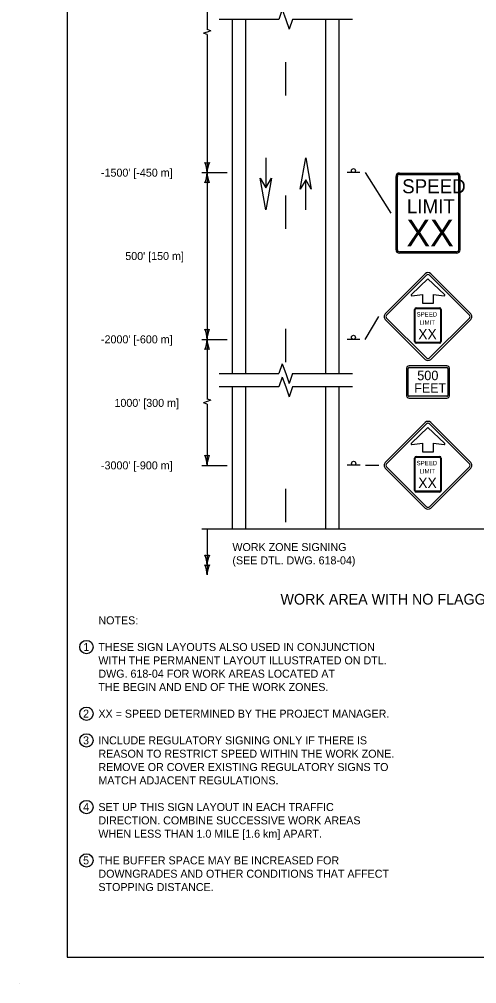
# Model space of a CAD drawing. Extents: x 49991.4 to 50021, y 49987.6 to 50011.4.
# Drawn here: x 49999.98 to 50003.41, y 49999.86 to 50007.09 of the extents above; entities that cross this region are included whole.
import ezdxf

# ---------------------------------------------------------------- set-up
doc = ezdxf.new("R2010")
doc.units = 0
for name, color, linetype in [('Level 1', 7, 'Continuous'), ('Level 2', 7, 'Continuous'), ('Level 3', 7, 'Continuous'), ('Level 6', 7, 'Continuous')]:
    doc.layers.add(name, color=color, linetype=linetype)

msp = doc.modelspace()

# ---------------------------------------------------------------- linework, layer by layer
at = {"layer": 'Level 1'}
for p, q in [((50001.5753, 50004.4375), (50001.5753, 50007.0935)), ((50001.6753, 50004.4375), (50001.6753, 50007.0935)), ((50002.2753, 50004.4375), (50002.2753, 50007.0935)), ((50002.3753, 50004.4375), (50002.3753, 50007.0935)), ((50001.9755, 50006.5231), (50001.9755, 50006.7731)), ((50001.8253, 50006.0559), (50001.8253, 50005.83)), ((50001.8257, 50006.0559), (50001.8257, 50005.83)), ((50002.5313, 50005.9443), (50002.4353, 50005.9443)), ((50002.8274, 50005.9412), (50003.2574, 50005.9412)), ((50002.8274, 50005.9312), (50003.2574, 50005.9312)), ((50002.1251, 50005.6657), (50002.1251, 50005.8916)), ((50002.1253, 50005.6657), (50002.1253, 50005.8916)), ((50002.8024, 50005.3662), (50002.8024, 50005.9162)), ((50002.8124, 50005.3662), (50002.8124, 50005.9162)), ((50003.2724, 50005.9162), (50003.2724, 50005.3662)), ((50003.2824, 50005.9162), (50003.2824, 50005.3662)), ((50001.9755, 50005.5231), (50001.9755, 50005.7731)), ((50003.2574, 50005.3512), (50002.8274, 50005.3512)), ((50003.2574, 50005.3412), (50002.8274, 50005.3412)), ((50003.021, 50005.1858), (50002.7217, 50004.8865)), ((50003.0311, 50005.1757), (50002.7318, 50004.8764)), ((50003.0424, 50005.1473), (50002.918, 50005.03)), ((50003.021, 50005.1858), (50003.021, 50005.1858)), ((50003.0311, 50005.1757), (50003.0311, 50005.1757)), ((50003.1668, 50005.03), (50003.0424, 50005.1473)), ((50003.353, 50004.8764), (50003.0537, 50005.1757)), ((50003.3631, 50004.8865), (50003.0638, 50005.1858)), ((50002.9221, 50005.0214), (50003.0021, 50005.0314)), ((50003.0021, 50005.0314), (50003.0021, 50004.9659)), ((50003.0827, 50004.9659), (50003.0827, 50005.0314)), ((50003.0827, 50005.0314), (50003.1627, 50005.0214)), ((50002.9421, 50004.677), (50002.9421, 50004.9183)), ((50002.9473, 50004.677), (50002.9473, 50004.9183)), ((50002.9545, 50004.9308), (50003.1293, 50004.9308)), ((50002.9545, 50004.9256), (50003.1293, 50004.9256)), ((50003.0021, 50004.9659), (50003.0827, 50004.9659)), ((50003.0419, 50004.9308), (50003.0419, 50004.9308)), ((50003.1365, 50004.9183), (50003.1365, 50004.677)), ((50003.1417, 50004.9183), (50003.1417, 50004.677)), ((50002.7318, 50004.8538), (50003.0311, 50004.5545)), ((50003.0537, 50004.5545), (50003.353, 50004.8538)), ((50001.9755, 50004.5231), (50001.9755, 50004.7731)), ((50002.7217, 50004.8437), (50003.021, 50004.5444)), ((50003.0638, 50004.5444), (50003.3631, 50004.8437)), ((50002.5313, 50004.6943), (50002.4353, 50004.6943)), ((50003.1293, 50004.6697), (50002.9545, 50004.6697)), ((50003.1293, 50004.6645), (50002.9545, 50004.6645)), ((50003.1835, 50004.4955), (50002.9013, 50004.4955)), ((50002.8811, 50004.4754), (50002.8811, 50004.2738)), ((50002.8946, 50004.2738), (50002.8946, 50004.4754)), ((50002.9013, 50004.4821), (50003.1835, 50004.4821)), ((50003.1903, 50004.4754), (50003.1903, 50004.2738)), ((50003.2037, 50004.2738), (50003.2037, 50004.4754)), ((50001.5752, 50003.2739), (50001.5752, 50004.3375)), ((50001.6752, 50003.2739), (50001.6752, 50004.3375)), ((50002.2752, 50003.2739), (50002.2752, 50004.3375)), ((50002.3752, 50003.2739), (50002.3752, 50004.3375)), ((50003.1835, 50004.267), (50002.9013, 50004.267)), ((50002.9013, 50004.2536), (50003.1835, 50004.2536)), ((50003.021, 50004.0707), (50002.7217, 50003.7714)), ((50003.0311, 50004.0606), (50002.7318, 50003.7613)), ((50003.021, 50004.0707), (50003.021, 50004.0707)), ((50003.0311, 50004.0606), (50003.0311, 50004.0606)), ((50003.353, 50003.7613), (50003.0537, 50004.0606)), ((50003.3631, 50003.7714), (50003.0638, 50004.0707)), ((50003.0424, 50004.0323), (50002.918, 50003.915)), ((50003.1668, 50003.915), (50003.0424, 50004.0323)), ((50002.9221, 50003.9063), (50003.0021, 50003.9163)), ((50003.0021, 50003.9163), (50003.0021, 50003.8508)), ((50003.0827, 50003.8508), (50003.0827, 50003.9163)), ((50003.0827, 50003.9163), (50003.1627, 50003.9063)), ((50003.0021, 50003.8508), (50003.0827, 50003.8508)), ((50002.9421, 50003.562), (50002.9421, 50003.8033)), ((50002.9473, 50003.562), (50002.9473, 50003.8033)), ((50002.9545, 50003.8157), (50003.1293, 50003.8157)), ((50002.9545, 50003.8105), (50003.1293, 50003.8105)), ((50003.0419, 50003.8157), (50003.0419, 50003.8157)), ((50003.1365, 50003.8033), (50003.1365, 50003.562)), ((50003.1417, 50003.8033), (50003.1417, 50003.562)), ((50002.5329, 50003.75), (50002.4369, 50003.75)), ((50002.7217, 50003.7286), (50003.021, 50003.4293)), ((50002.7318, 50003.7387), (50003.0311, 50003.4394)), ((50003.0537, 50003.4394), (50003.353, 50003.7387)), ((50003.0638, 50003.4293), (50003.3631, 50003.7286)), ((50001.9755, 50003.3226), (50001.9755, 50003.5726)), ((50003.1293, 50003.5547), (50002.9545, 50003.5547)), ((50003.1293, 50003.5495), (50002.9545, 50003.5495)), ((49999.9766, 49999.8624), (49999.9766, 49999.8624))]:
    msp.add_line(p, q, dxfattribs=at)
for points in [[(50008.6146, 50011.2628), (50000.3356, 50011.2628), (50000.3356, 50000.0624), (50008.6146, 50000.0624)], [(50002.0833, 50005.8193), (50002.1251, 50006.0558), (50002.1669, 50005.8193), (50002.1251, 50005.8915)], [(50001.8673, 50005.9023), (50001.8257, 50005.6658), (50001.7837, 50005.9023), (50001.8257, 50005.8301)]]:
    msp.add_lwpolyline(points, close=True, dxfattribs=at)
for centre in [(50002.4833, 50005.9595), (50002.4833, 50004.7095), (50002.4848, 50003.7652)]:
    msp.add_circle(centre, 0.0152, dxfattribs=at)
for centre, radius, start, end in [((50002.8275, 50005.9162), 0.025, 90, 180), ((50002.8275, 50005.9162), 0.015, 90, 180), ((50003.2575, 50005.9162), 0.025, 0, 90), ((50003.2575, 50005.9162), 0.015, 0, 90), ((50002.8275, 50005.3662), 0.025, 180, 270), ((50002.8275, 50005.3662), 0.015, 180, 270), ((50003.2575, 50005.3662), 0.025, 270, 0), ((50003.2575, 50005.3662), 0.015, 270, 0), ((50003.0424, 50005.1644), 0.0302, 45.00007, 134.99993), ((50003.0424, 50005.1644), 0.016, 45.00007, 134.99993), ((50002.9216, 50005.0264), 0.00508, 134.62874, 275.82948), ((50003.1632, 50005.0264), 0.00509, 264.38259, 45.16491), ((50002.9545, 50004.9183), 0.0125, 90, 180), ((50002.9545, 50004.9183), 0.00728, 90, 180), ((50003.1293, 50004.9183), 0.0125, 360, 90), ((50003.1293, 50004.9183), 0.00728, 360, 90), ((50002.7431, 50004.8651), 0.0302, 134.99993, 225.00008), ((50002.7431, 50004.8651), 0.016, 134.99993, 225.00008), ((50003.3417, 50004.8651), 0.016, 314.99993, 45.00007), ((50003.3417, 50004.8651), 0.0302, 314.99993, 45.00008), ((50002.9545, 50004.677), 0.0125, 180, 270), ((50002.9545, 50004.677), 0.00728, 180, 270), ((50003.1293, 50004.677), 0.00728, 270, 360), ((50003.1293, 50004.677), 0.0125, 270, 360), ((50002.9013, 50004.4754), 0.0202, 90, 180), ((50003.0424, 50004.5658), 0.0302, 225.00007, 314.99993), ((50003.0424, 50004.5658), 0.016, 225.00007, 314.99993), ((50003.1835, 50004.4754), 0.0202, 0, 90), ((50002.9013, 50004.4754), 0.00672, 90, 180), ((50003.1835, 50004.4754), 0.00672, 0, 90), ((50002.9013, 50004.2738), 0.0202, 180, 270), ((50002.9013, 50004.2738), 0.00672, 180, 270), ((50003.1835, 50004.2738), 0.00672, 270, 360), ((50003.1835, 50004.2738), 0.0202, 270, 360), ((50003.0424, 50004.0493), 0.0302, 45.00007, 134.99993), ((50003.0424, 50004.0493), 0.016, 45.00007, 134.99993), ((50002.9216, 50003.9113), 0.00508, 134.62874, 275.82948), ((50003.1632, 50003.9113), 0.00509, 264.38259, 45.16491), ((50002.7431, 50003.75), 0.0302, 134.99993, 225.00008), ((50002.7431, 50003.75), 0.016, 134.99993, 225.00008), ((50002.9545, 50003.8033), 0.0125, 90, 180), ((50002.9545, 50003.8033), 0.00728, 90, 180), ((50003.1293, 50003.8033), 0.0125, 360, 90), ((50003.1293, 50003.8033), 0.00728, 360, 90), ((50003.3417, 50003.75), 0.016, 314.99993, 45.00007), ((50003.3417, 50003.75), 0.0302, 314.99993, 45.00008), ((50002.9545, 50003.562), 0.0125, 180, 270), ((50002.9545, 50003.562), 0.00728, 180, 270), ((50003.1293, 50003.562), 0.00728, 270, 360), ((50003.1293, 50003.562), 0.0125, 270, 360), ((50003.0424, 50003.4507), 0.0302, 225.00007, 314.99993), ((50003.0424, 50003.4507), 0.016, 225.00007, 314.99993)]:
    msp.add_arc(centre, radius, start, end, dxfattribs=at)
at = {"layer": 'Level 2'}
for centre in [(50000.4801, 50002.3872), (50000.4801, 50001.8872), (50000.4801, 50001.6872), (50000.4801, 50001.1872), (50000.4801, 50000.7872)]:
    msp.add_circle(centre, 0.05, dxfattribs=at)
at = {"layer": 'Level 3'}
for p, q in [((50001.3853, 50008.5052), (50001.3853, 50007.0182)), ((50001.4127, 50007.0085), (50001.3853, 50007.0182)), ((50001.3853, 50006.9988), (50001.3579, 50006.9891)), ((50001.3853, 50006.9794), (50001.3579, 50006.9891)), ((50001.4127, 50007.0085), (50001.3853, 50006.9988)), ((50001.3853, 50006.9794), (50001.3853, 50006.5693)), ((50001.3853, 50006.5693), (50001.3853, 50005.9443)), ((50001.3453, 50005.9443), (50001.5353, 50005.9443)), ((50001.3853, 50005.9443), (50001.3853, 50004.6943)), ((50002.5713, 50005.9443), (50002.7624, 50005.6412)), ((50002.5713, 50004.6943), (50002.6729, 50004.8651)), ((50001.3453, 50004.6943), (50001.5353, 50004.6943)), ((50001.3853, 50004.6943), (50001.3853, 50004.2469)), ((50001.3853, 50004.2275), (50001.3579, 50004.2178)), ((50001.3853, 50004.2081), (50001.3579, 50004.2178)), ((50001.4127, 50004.2372), (50001.3853, 50004.2469)), ((50001.4127, 50004.2372), (50001.3853, 50004.2275)), ((50001.3853, 50004.2081), (50001.3853, 50003.7492)), ((50001.3453, 50003.7492), (50001.5352, 50003.7492)), ((50002.5729, 50003.75), (50002.6729, 50003.75)), ((50001.3453, 50003.2739), (50004.3393, 50003.2739)), ((50001.3853, 50003.2739), (50001.3853, 50002.9277))]:
    msp.add_line(p, q, dxfattribs=at)
for centre, radius, start, end in [((50001.3853, 50006.0725), 0.0548, 252.13882, 287.86118), ((50001.1526, 50005.9328), 0.233, 2.82731, 22.07716), ((50001.6075, 50005.9352), 0.2223, 157.45601, 177.63952), ((50001.1632, 50005.9535), 0.2223, 337.45601, 357.63952), ((50001.618, 50005.9558), 0.233, 182.82731, 202.07716), ((50001.3853, 50005.8161), 0.0548, 72.13882, 107.86118), ((50001.1632, 50004.6852), 0.2223, 2.36048, 22.54399), ((50001.3853, 50004.8225), 0.0548, 252.13882, 287.86118), ((50001.618, 50004.6828), 0.233, 157.92284, 177.17269), ((50001.1632, 50004.7035), 0.2223, 337.45601, 357.63952), ((50001.618, 50004.7058), 0.233, 182.82731, 202.07716), ((50001.3853, 50004.5661), 0.0548, 72.13882, 107.86118), ((50001.1632, 50003.74), 0.2223, 2.36048, 22.54399), ((50001.3853, 50003.8774), 0.0548, 252.13882, 287.86118), ((50001.618, 50003.7377), 0.233, 157.92284, 177.17269), ((50001.3853, 50003.1293), 0.0548, 252.13882, 287.86118), ((50001.1526, 50002.9896), 0.233, 2.82731, 22.07716), ((50001.6075, 50002.9919), 0.2223, 157.45601, 177.63952), ((50001.3853, 50003.0559), 0.0548, 252.13882, 287.86118), ((50001.1526, 50002.9162), 0.233, 2.82731, 22.07716), ((50001.6075, 50002.9185), 0.2223, 157.45601, 177.63952)]:
    msp.add_arc(centre, radius, start, end, dxfattribs=at)
at = {"layer": 'Level 6'}
for p, q in [((50001.9494, 50007.1666), (50001.9235, 50007.0935)), ((50001.9494, 50007.1666), (50001.9753, 50007.0935)), ((50001.9235, 50007.0935), (50001.4753, 50007.0935)), ((50001.9753, 50007.0935), (50002.0012, 50007.0204)), ((50002.0271, 50007.0935), (50002.0012, 50007.0204)), ((50002.4753, 50007.0935), (50002.0271, 50007.0935)), ((50001.9495, 50004.5106), (50001.9235, 50004.4375)), ((50001.9495, 50004.5106), (50001.9753, 50004.4375)), ((50001.4753, 50004.4375), (50001.9235, 50004.4375)), ((50001.9494, 50004.4106), (50001.9234, 50004.3375)), ((50001.9494, 50004.4106), (50001.9752, 50004.3375)), ((50001.9753, 50004.4375), (50002.0013, 50004.3644)), ((50002.0271, 50004.4375), (50002.0013, 50004.3644)), ((50002.0271, 50004.4375), (50002.4753, 50004.4375)), ((50001.9234, 50004.3375), (50001.4752, 50004.3375)), ((50001.9752, 50004.3375), (50002.0012, 50004.2644)), ((50002.027, 50004.3375), (50002.0012, 50004.2644)), ((50002.4752, 50004.3375), (50002.027, 50004.3375))]:
    msp.add_line(p, q, dxfattribs=at)

# ---------------------------------------------------------------- texts
at = {"layer": 'Level 1'}
for s, height, p in [('SPEED', 0.10512, (50002.8487, 50005.7897)), ('LIMIT', 0.10512, (50002.8841, 50005.6396)), ('XX', 0.1989, (50002.8809, 50005.3923)), ('500', 0.07124, (50002.9615, 50004.388)), ('FEET', 0.06989, (50002.9391, 50004.2939))]:
    msp.add_text(s, height=height, dxfattribs=at).set_placement(p)
for s, height, p in [('SPEED', 0.03301, (50002.9566, 50004.8651)), ('XX', 0.07775, (50002.9694, 50004.6947)), ('LIMIT', 0.03301, (50002.9784, 50004.8041)), ('SPEED', 0.03301, (50002.9566, 50003.75)), ('LIMIT', 0.03301, (50002.9784, 50003.689)), ('XX', 0.07775, (50002.9694, 50003.5796))]:
    msp.add_text(s, height=height, rotation=360, dxfattribs=at).set_placement(p)
at = {"layer": 'Level 2'}
for s, height, p in [("-1500' [-450 m]", 0.06, (50000.5895, 50005.9143)), ("500' [150 m]", 0.06, (50000.772, 50005.2893)), ("-2000' [-600 m]", 0.06, (50000.5895, 50004.6643)), ("1000' [300 m]", 0.06, (50000.6907, 50004.1878)), ("-3000' [-900 m]", 0.06, (50000.5895, 50003.7192)), ('WORK ZONE SIGNING', 0.06, (50001.5753, 50003.1069)), ('(SEE DTL. DWG. 618-04)', 0.06, (50001.5753, 50003.0069)), ('WORK AREA WITH NO FLAGGER', 0.08, (50001.936, 50002.7055)), ('NOTES:', 0.06, (50000.5701, 50002.5572)), ('1', 0.06, (50000.4574, 50002.3572)), ('THESE SIGN LAYOUTS ALSO USED IN CONJUNCTION', 0.06, (50000.5701, 50002.3572)), ('WITH THE PERMANENT LAYOUT ILLUSTRATED ON DTL. ', 0.06, (50000.5701, 50002.2572)), ('DWG. 618-04 FOR WORK AREAS LOCATED AT', 0.06, (50000.5701, 50002.1572)), ('THE BEGIN AND END OF THE WORK ZONES.', 0.06, (50000.5701, 50002.0572)), ('2', 0.06, (50000.4549, 50001.8572)), ('XX = SPEED DETERMINED BY THE PROJECT MANAGER.', 0.06, (50000.5701, 50001.8572)), ('3', 0.06, (50000.4549, 50001.6572)), ('INCLUDE REGULATORY SIGNING ONLY IF THERE IS ', 0.06, (50000.5701, 50001.6572)), ('REASON TO RESTRICT SPEED WITHIN THE WORK ZONE.', 0.06, (50000.5701, 50001.5572)), ('REMOVE OR COVER EXISTING REGULATORY SIGNS TO', 0.06, (50000.5701, 50001.4572)), ('MATCH ADJACENT REGULATIONS.', 0.06, (50000.5701, 50001.3572)), ('4', 0.06, (50000.4561, 50001.1572)), ('SET UP THIS SIGN LAYOUT IN EACH TRAFFIC ', 0.06, (50000.5701, 50001.1572)), ('DIRECTION. COMBINE SUCCESSIVE WORK AREAS', 0.06, (50000.5701, 50001.0572)), ('WHEN LESS THAN 1.0 MILE [1.6 km] APART.', 0.06, (50000.5701, 50000.9572)), ('5', 0.06, (50000.4552, 50000.7572)), ('THE BUFFER SPACE MAY BE INCREASED FOR', 0.06, (50000.5701, 50000.7572)), ('DOWNGRADES AND OTHER CONDITIONS THAT AFFECT', 0.06, (50000.5701, 50000.6572)), ('STOPPING DISTANCE.', 0.06, (50000.5701, 50000.5572))]:
    msp.add_text(s, height=height, dxfattribs=at).set_placement(p)

doc.saveas('drawing.dxf')
